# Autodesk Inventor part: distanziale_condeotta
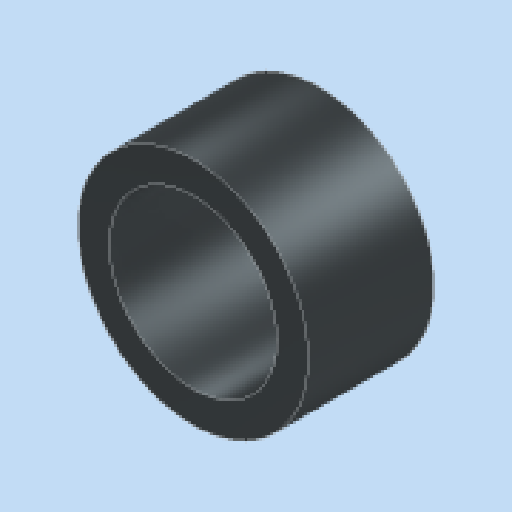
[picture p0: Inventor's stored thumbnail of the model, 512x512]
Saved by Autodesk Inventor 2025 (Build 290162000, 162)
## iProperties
Created: 2026-05
Part Number: distanziale_condeotta
Material: Bronzo, Stagno dolce
Document SubType Name: Modeling
Designer: R5800u
Density: 8.874 g/cm^3
Appearance: Grigio ferro
Author: R5800u
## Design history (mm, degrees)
sketch "Schizzo1"
  geometry: C1 r 20 at (0, 0); C2 r 27.5 at (0, 0); 1 further point
  constraints: 2 centre point, 1 coincident
  dimensions: "d0" = 40 diameter of C1; "d1" = 7.5 radial gap between concentric circles of C1 C2
extrude "Estrusione1" new body sketch "Schizzo1" distance "d2" = 30; taper "d3" = 0 deg
node "Solido1"
